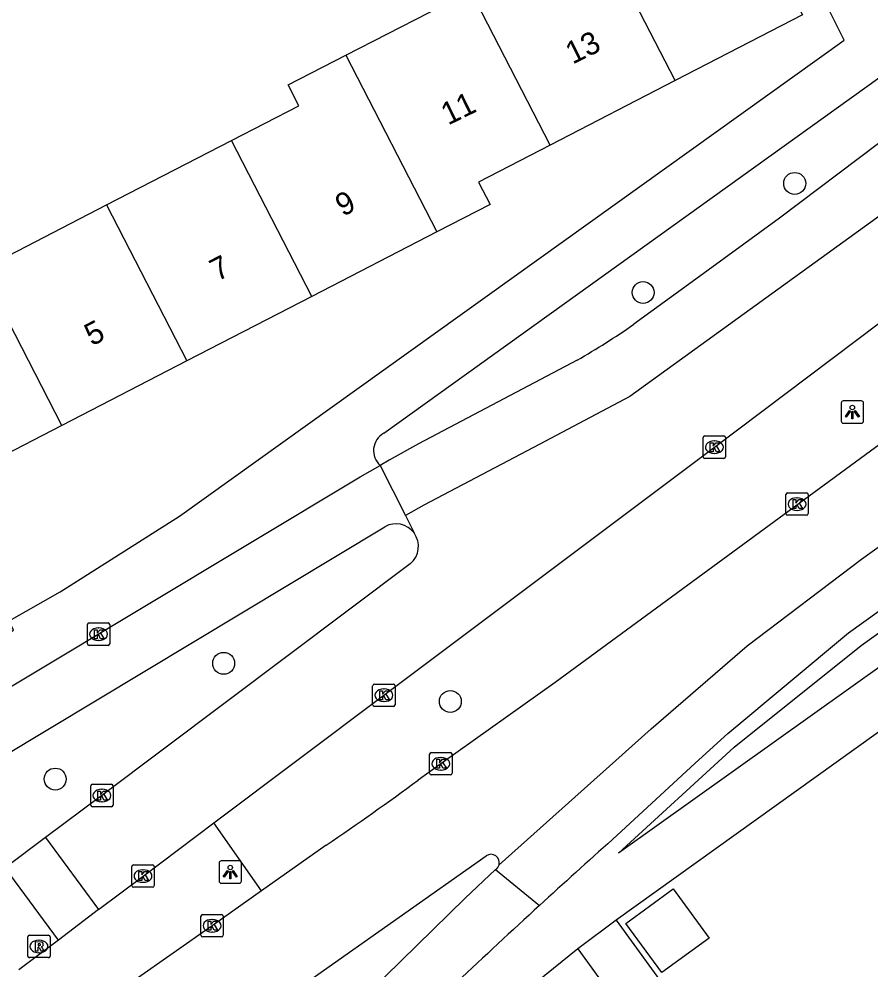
# Model space of a CAD drawing. Extents: x 158461 to 159795, y 387220 to 388672.
# Drawn here: x 159193.22 to 159231.25, y 387763.85 to 387806.3 of the extents above; entities that cross this region are included whole.
import ezdxf

# ---------------------------------------------------------------- set-up
doc = ezdxf.new("R2010")
doc.units = 0
for name, color, linetype in [('IMGEO_Berm_groen', 7, 'Continuous'), ('IMGEO_Boom', 7, 'Continuous'), ('IMGEO_Fietspad_open', 7, 'Continuous'), ('IMGEO_Kolk', 7, 'Continuous'), ('IMGEO_Lichtpunt', 7, 'Continuous'), ('IMGEO_Muur', 7, 'Continuous'), ('IMGEO_Pand', 7, 'Continuous'), ('IMGEO_Pand_nummerreeks', 7, 'Continuous'), ('IMGEO_Rijbaan_lokaal_gesloten', 7, 'Continuous'), ('IMGEO_Rioolput', 7, 'Continuous'), ('IMGEO_Voetpad_open', 7, 'Continuous')]:
    doc.layers.add(name, color=color, linetype=linetype)

msp = doc.modelspace()

# ---------------------------------------------------------------- linework, layer by layer
at = {"layer": 'IMGEO_Berm_groen'}
msp.add_lwpolyline([(159204.04, 387767.381), (159201.915, 387770.417)], dxfattribs=at)
at = {"layer": 'IMGEO_Boom'}
for centre in [(159227.844, 387798.958), (159221.076, 387794.088), (159202.352, 387777.538), (159212.47, 387775.836), (159194.832, 387772.371)]:
    msp.add_circle(centre, 0.489, dxfattribs=at)
at = {"layer": 'IMGEO_Fietspad_open'}
for points in [[(159183.546, 387770.917), (159187.81, 387773.495), (159188.686, 387774.005), (159208.439, 387785.867), (159208.888, 387786.12), (159209.337, 387786.373)], [(159189.389, 387771.511), (159190.225, 387772.028), (159209.549, 387783.637)], [(159214.491, 387768.328), (159213.131, 387767.053), (159199.59, 387753.792), (159198.894, 387753.089), (159198.822, 387753.027)]]:
    msp.add_lwpolyline(points, dxfattribs=at)
for centre, radius, start, end in [((159210.04, 387782.757), 1.007, 36.5326, 119.1576), ((159441.931, 387520.228), 334.072, 132.45033, 134.17723)]:
    msp.add_arc(centre, radius, start, end, dxfattribs=at)
at = {"layer": 'IMGEO_Kolk'}
for p, q in [((159223.756, 387786.758), (159223.756, 387787.61)), ((159223.831, 387787.684), (159224.683, 387787.684)), ((159224.757, 387787.61), (159224.757, 387786.758)), ((159224.244, 387787.464), (159224.269, 387787.464)), ((159224.683, 387786.684), (159223.831, 387786.684)), ((159224.267, 387786.904), (159224.242, 387786.904)), ((159227.449, 387784.218), (159227.449, 387785.07)), ((159227.524, 387785.144), (159228.376, 387785.144)), ((159228.45, 387785.07), (159228.45, 387784.218)), ((159227.937, 387784.924), (159227.962, 387784.924)), ((159228.376, 387784.144), (159227.524, 387784.144)), ((159227.96, 387784.364), (159227.935, 387784.364)), ((159196.267, 387778.412), (159196.267, 387779.264)), ((159196.342, 387779.338), (159197.194, 387779.338)), ((159196.755, 387779.118), (159196.78, 387779.118)), ((159197.268, 387779.264), (159197.268, 387778.412)), ((159197.194, 387778.338), (159196.342, 387778.338)), ((159196.778, 387778.558), (159196.753, 387778.558)), ((159209.003, 387775.686), (159209.003, 387776.538)), ((159209.078, 387776.612), (159209.93, 387776.612)), ((159210.004, 387776.538), (159210.004, 387775.686)), ((159209.491, 387776.392), (159209.516, 387776.392)), ((159209.514, 387775.832), (159209.489, 387775.832)), ((159209.93, 387775.612), (159209.078, 387775.612)), ((159211.622, 387773.554), (159212.474, 387773.554)), ((159211.547, 387772.628), (159211.547, 387773.48)), ((159212.035, 387773.334), (159212.06, 387773.334)), ((159212.548, 387773.48), (159212.548, 387772.628)), ((159212.058, 387772.774), (159212.033, 387772.774)), ((159212.474, 387772.554), (159211.622, 387772.554)), ((159196.415, 387771.211), (159196.415, 387772.063)), ((159196.49, 387772.137), (159197.342, 387772.137)), ((159196.903, 387771.917), (159196.928, 387771.917)), ((159197.416, 387772.063), (159197.416, 387771.211)), ((159197.342, 387771.137), (159196.49, 387771.137)), ((159196.926, 387771.357), (159196.901, 387771.357)), ((159198.25, 387767.616), (159198.25, 387768.468)), ((159198.325, 387768.542), (159199.177, 387768.542)), ((159199.251, 387768.468), (159199.251, 387767.616)), ((159198.738, 387768.322), (159198.763, 387768.322)), ((159198.761, 387767.762), (159198.736, 387767.762)), ((159199.177, 387767.542), (159198.325, 387767.542)), ((159201.41, 387766.324), (159202.262, 387766.324)), ((159201.335, 387765.398), (159201.335, 387766.25)), ((159201.823, 387766.104), (159201.848, 387766.104)), ((159202.336, 387766.25), (159202.336, 387765.398)), ((159201.846, 387765.544), (159201.821, 387765.544)), ((159202.262, 387765.324), (159201.41, 387765.324))]:
    msp.add_line(p, q, dxfattribs=at)
for points in [[(159223.756, 387786.758), (159223.756, 387787.61)], [(159223.831, 387787.684), (159224.683, 387787.684)], [(159224.757, 387787.61), (159224.757, 387786.758)], [(159224.077, 387787.384), (159224.2, 387787.384), (159224.2, 387787.233), (159224.33, 387787.384), (159224.494, 387787.384), (159224.348, 387787.233), (159224.501, 387786.984), (159224.349, 387786.984), (159224.264, 387787.148), (159224.2, 387787.081), (159224.2, 387786.984), (159224.077, 387786.984), (159224.077, 387787.384)], [(159224.683, 387786.684), (159223.831, 387786.684)], [(159227.449, 387784.218), (159227.449, 387785.07)], [(159227.524, 387785.144), (159228.376, 387785.144)], [(159228.45, 387785.07), (159228.45, 387784.218)], [(159227.77, 387784.844), (159227.893, 387784.844), (159227.893, 387784.693), (159228.023, 387784.844), (159228.187, 387784.844), (159228.041, 387784.693), (159228.194, 387784.444), (159228.042, 387784.444), (159227.957, 387784.608), (159227.893, 387784.541), (159227.893, 387784.444), (159227.77, 387784.444), (159227.77, 387784.844)], [(159228.376, 387784.144), (159227.524, 387784.144)], [(159196.267, 387778.412), (159196.267, 387779.264)], [(159196.342, 387779.338), (159197.194, 387779.338)], [(159197.268, 387779.264), (159197.268, 387778.412)], [(159196.588, 387779.038), (159196.711, 387779.038), (159196.711, 387778.887), (159196.841, 387779.038), (159197.005, 387779.038), (159196.859, 387778.887), (159197.012, 387778.638), (159196.86, 387778.638), (159196.775, 387778.802), (159196.711, 387778.735), (159196.711, 387778.638), (159196.588, 387778.638), (159196.588, 387779.038)], [(159197.194, 387778.338), (159196.342, 387778.338)], [(159209.003, 387775.686), (159209.003, 387776.538)], [(159209.078, 387776.612), (159209.93, 387776.612)], [(159210.004, 387776.538), (159210.004, 387775.686)], [(159209.324, 387776.312), (159209.447, 387776.312), (159209.447, 387776.161), (159209.577, 387776.312), (159209.741, 387776.312), (159209.595, 387776.161), (159209.748, 387775.912), (159209.596, 387775.912), (159209.511, 387776.076), (159209.447, 387776.009), (159209.447, 387775.912), (159209.324, 387775.912), (159209.324, 387776.312)], [(159209.93, 387775.612), (159209.078, 387775.612)], [(159211.622, 387773.554), (159212.474, 387773.554)], [(159211.547, 387772.628), (159211.547, 387773.48)], [(159211.868, 387773.254), (159211.991, 387773.254), (159211.991, 387773.103), (159212.121, 387773.254), (159212.285, 387773.254), (159212.139, 387773.103), (159212.292, 387772.854), (159212.14, 387772.854), (159212.055, 387773.018), (159211.991, 387772.951), (159211.991, 387772.854), (159211.868, 387772.854), (159211.868, 387773.254)], [(159212.548, 387773.48), (159212.548, 387772.628)], [(159212.474, 387772.554), (159211.622, 387772.554)], [(159196.415, 387771.211), (159196.415, 387772.063)], [(159196.49, 387772.137), (159197.342, 387772.137)], [(159196.736, 387771.837), (159196.859, 387771.837), (159196.859, 387771.686), (159196.989, 387771.837), (159197.153, 387771.837), (159197.007, 387771.686), (159197.16, 387771.437), (159197.008, 387771.437), (159196.923, 387771.601), (159196.859, 387771.534), (159196.859, 387771.437), (159196.736, 387771.437), (159196.736, 387771.837)], [(159197.416, 387772.063), (159197.416, 387771.211)], [(159197.342, 387771.137), (159196.49, 387771.137)], [(159198.25, 387767.616), (159198.25, 387768.468)], [(159198.325, 387768.542), (159199.177, 387768.542)], [(159199.251, 387768.468), (159199.251, 387767.616)], [(159198.571, 387768.242), (159198.694, 387768.242), (159198.694, 387768.091), (159198.824, 387768.242), (159198.988, 387768.242), (159198.842, 387768.091), (159198.995, 387767.842), (159198.843, 387767.842), (159198.758, 387768.006), (159198.694, 387767.939), (159198.694, 387767.842), (159198.571, 387767.842), (159198.571, 387768.242)], [(159199.177, 387767.542), (159198.325, 387767.542)], [(159201.41, 387766.324), (159202.262, 387766.324)], [(159201.335, 387765.398), (159201.335, 387766.25)], [(159201.656, 387766.024), (159201.779, 387766.024), (159201.779, 387765.873), (159201.909, 387766.024), (159202.073, 387766.024), (159201.927, 387765.873), (159202.08, 387765.624), (159201.928, 387765.624), (159201.843, 387765.788), (159201.779, 387765.721), (159201.779, 387765.624), (159201.656, 387765.624), (159201.656, 387766.024)], [(159202.336, 387766.25), (159202.336, 387765.398)], [(159202.262, 387765.324), (159201.41, 387765.324)]]:
    msp.add_lwpolyline(points, dxfattribs=at)
for centre, start, end in [((159223.833, 387787.608), 91.552, 178.448), ((159223.833, 387787.608), 91.552, 178.448), ((159224.681, 387787.608), 1.552, 88.448), ((159224.681, 387787.608), 1.552, 88.448), ((159223.833, 387786.76), 181.552, 268.448), ((159223.833, 387786.76), 181.552, 268.448), ((159224.681, 387786.76), 271.552, 358.448), ((159224.681, 387786.76), 271.552, 358.448), ((159227.526, 387785.068), 91.552, 178.448), ((159227.526, 387785.068), 91.552, 178.448), ((159228.374, 387785.068), 1.552, 88.448), ((159228.374, 387785.068), 1.552, 88.448), ((159227.526, 387784.22), 181.552, 268.448), ((159227.526, 387784.22), 181.552, 268.448), ((159228.374, 387784.22), 271.552, 358.448), ((159228.374, 387784.22), 271.552, 358.448), ((159196.344, 387779.262), 91.552, 178.448), ((159196.344, 387779.262), 91.552, 178.448), ((159197.192, 387779.262), 1.552, 88.448), ((159197.192, 387779.262), 1.552, 88.448), ((159196.344, 387778.414), 181.552, 268.448), ((159196.344, 387778.414), 181.552, 268.448), ((159197.192, 387778.414), 271.552, 358.448), ((159197.192, 387778.414), 271.552, 358.448), ((159209.08, 387776.536), 91.552, 178.448), ((159209.08, 387776.536), 91.552, 178.448), ((159209.928, 387776.536), 1.552, 88.448), ((159209.928, 387776.536), 1.552, 88.448), ((159209.08, 387775.688), 181.552, 268.448), ((159209.08, 387775.688), 181.552, 268.448), ((159209.928, 387775.688), 271.552, 358.448), ((159209.928, 387775.688), 271.552, 358.448), ((159211.624, 387773.478), 91.552, 178.448), ((159211.624, 387773.478), 91.552, 178.448), ((159212.472, 387773.478), 1.552, 88.448), ((159212.472, 387773.478), 1.552, 88.448), ((159211.624, 387772.63), 181.552, 268.448), ((159211.624, 387772.63), 181.552, 268.448), ((159212.472, 387772.63), 271.552, 358.448), ((159212.472, 387772.63), 271.552, 358.448), ((159196.492, 387772.061), 91.552, 178.448), ((159196.492, 387772.061), 91.552, 178.448), ((159197.34, 387772.061), 1.552, 88.448), ((159197.34, 387772.061), 1.552, 88.448), ((159196.492, 387771.213), 181.552, 268.448), ((159196.492, 387771.213), 181.552, 268.448), ((159197.34, 387771.213), 271.552, 358.448), ((159197.34, 387771.213), 271.552, 358.448), ((159198.327, 387768.466), 91.552, 178.448), ((159198.327, 387768.466), 91.552, 178.448), ((159199.175, 387768.466), 1.552, 88.448), ((159199.175, 387768.466), 1.552, 88.448), ((159198.327, 387767.618), 181.552, 268.448), ((159198.327, 387767.618), 181.552, 268.448), ((159199.175, 387767.618), 271.552, 358.448), ((159199.175, 387767.618), 271.552, 358.448), ((159201.412, 387766.248), 91.552, 178.448), ((159201.412, 387766.248), 91.552, 178.448), ((159202.26, 387766.248), 1.552, 88.448), ((159202.26, 387766.248), 1.552, 88.448), ((159201.412, 387765.4), 181.552, 268.448), ((159201.412, 387765.4), 181.552, 268.448), ((159202.26, 387765.4), 271.552, 358.448), ((159202.26, 387765.4), 271.552, 358.448)]:
    msp.add_arc(centre, 0.0765, start, end, dxfattribs=at)
for centre, major_axis, ratio, start_param, end_param in [((159224.243, 387787.184), (-0.387, 0.002), 0.722429, 4.712389, 7.853982), ((159224.268, 387787.184), (-0.39, 0.002), 0.717154, 1.570796, 4.712389), ((159227.936, 387784.644), (-0.387, 0.002), 0.722429, 4.712389, 7.853982), ((159227.961, 387784.644), (-0.39, 0.002), 0.717154, 1.570796, 4.712389), ((159196.754, 387778.838), (-0.387, 0.002), 0.722429, 4.712389, 7.853982), ((159196.779, 387778.838), (-0.39, 0.002), 0.717154, 1.570796, 4.712389), ((159209.49, 387776.112), (-0.387, 0.002), 0.722429, 4.712389, 7.853982), ((159209.515, 387776.112), (-0.39, 0.002), 0.717154, 1.570796, 4.712389), ((159212.034, 387773.054), (-0.387, 0.002), 0.722429, 4.712389, 7.853982), ((159212.059, 387773.054), (-0.39, 0.002), 0.717154, 1.570796, 4.712389), ((159196.902, 387771.637), (-0.387, 0.002), 0.722429, 4.712389, 7.853982), ((159196.927, 387771.637), (-0.39, 0.002), 0.717154, 1.570796, 4.712389), ((159198.737, 387768.042), (-0.387, 0.002), 0.722429, 4.712389, 7.853982), ((159198.762, 387768.042), (-0.39, 0.002), 0.717154, 1.570796, 4.712389), ((159201.822, 387765.824), (-0.387, 0.002), 0.722429, 4.712389, 7.853982), ((159201.847, 387765.824), (-0.39, 0.002), 0.717154, 1.570796, 4.712389)]:
    msp.add_ellipse(centre, major_axis=major_axis, ratio=ratio, start_param=start_param, end_param=end_param, dxfattribs=at)
at = {"layer": 'IMGEO_Lichtpunt'}
for p, q in [((159230.821, 387789.253), (159230.013, 387789.253)), ((159230.821, 387789.253), (159230.013, 387789.253)), ((159229.919, 387789.158), (159229.919, 387788.351)), ((159229.919, 387789.158), (159229.919, 387788.351)), ((159230.915, 387788.351), (159230.915, 387789.158)), ((159230.915, 387788.351), (159230.915, 387789.158)), ((159230.013, 387788.257), (159230.821, 387788.257)), ((159230.013, 387788.257), (159230.821, 387788.257)), ((159202.148, 387768.625), (159202.148, 387767.818)), ((159202.148, 387768.625), (159202.148, 387767.818)), ((159203.05, 387768.72), (159202.242, 387768.72)), ((159203.05, 387768.72), (159202.242, 387768.72)), ((159203.144, 387767.818), (159203.144, 387768.625)), ((159203.144, 387767.818), (159203.144, 387768.625)), ((159202.242, 387767.724), (159203.05, 387767.724)), ((159202.242, 387767.724), (159203.05, 387767.724))]:
    msp.add_line(p, q, dxfattribs=at)
for points in [[(159230.293, 387788.822), (159230.332, 387788.794), (159230.144, 387788.532), (159230.106, 387788.559), (159230.293, 387788.822)], [(159230.505, 387788.794), (159230.543, 387788.821), (159230.73, 387788.559), (159230.691, 387788.531), (159230.505, 387788.794)], [(159230.395, 387788.774), (159230.442, 387788.774), (159230.442, 387788.452), (159230.395, 387788.452), (159230.395, 387788.774)], [(159202.522, 387768.289), (159202.561, 387768.261), (159202.373, 387767.999), (159202.335, 387768.026), (159202.522, 387768.289)], [(159202.624, 387768.241), (159202.671, 387768.241), (159202.671, 387767.919), (159202.624, 387767.919), (159202.624, 387768.241)], [(159202.734, 387768.261), (159202.772, 387768.288), (159202.959, 387768.026), (159202.92, 387767.998), (159202.734, 387768.261)]]:
    msp.add_lwpolyline(points, dxfattribs=at)
for centre in [(159230.418, 387788.956), (159202.647, 387768.423)]:
    msp.add_circle(centre, 0.0994, dxfattribs=at)
for centre, start, end in [((159230.013, 387789.158), 90, 180), ((159230.013, 387789.158), 90, 180), ((159230.821, 387789.158), 0, 90), ((159230.821, 387789.158), 0, 90), ((159230.013, 387788.351), 180, 270), ((159230.013, 387788.351), 180, 270), ((159230.821, 387788.351), 270, 0), ((159230.821, 387788.351), 270, 360), ((159202.242, 387768.625), 90, 180), ((159202.242, 387768.625), 90, 180), ((159203.05, 387768.625), 0, 90), ((159203.05, 387768.625), 0, 90), ((159202.242, 387767.818), 180, 270), ((159202.242, 387767.818), 180, 270), ((159203.05, 387767.818), 270, 0), ((159203.05, 387767.818), 270, 360)]:
    msp.add_arc(centre, 0.0946, start, end, dxfattribs=at)
at = {"layer": 'IMGEO_Muur'}
msp.add_lwpolyline([(159303.107, 387825.734), (159219.866, 387766.077)], dxfattribs=at)
at = {"layer": 'IMGEO_Pand'}
for points in [[(159218.957, 387810.435), (159224.641, 387813.368), (159228.194, 387806.484), (159222.51, 387803.551)], [(159222.51, 387803.551), (159218.957, 387810.435)], [(159207.8, 387804.678), (159213.379, 387807.557)], [(159216.931, 387800.672), (159213.379, 387807.557)], [(159202.697, 387800.876), (159205.705, 387802.428), (159205.229, 387803.351), (159207.8, 387804.678)], [(159207.8, 387804.678), (159211.87, 387796.792)], [(159222.51, 387803.551), (159216.931, 387800.672)], [(159197.118, 387797.997), (159202.697, 387800.876)], [(159206.291, 387793.913), (159202.697, 387800.876)], [(159216.931, 387800.672), (159213.726, 387799.018), (159214.243, 387798.016), (159211.87, 387796.792)], [(159191.54, 387795.119), (159197.118, 387797.997)], [(159197.118, 387797.997), (159200.712, 387791.034)], [(159211.87, 387796.792), (159206.291, 387793.913)], [(159195.133, 387788.155), (159191.54, 387795.119)], [(159206.291, 387793.913), (159200.712, 387791.034)], [(159200.712, 387791.034), (159195.133, 387788.155)], [(159195.133, 387788.155), (159189.555, 387785.276)], [(159224.026, 387765.272), (159221.912, 387763.731), (159220.309, 387765.93), (159222.423, 387767.471), (159224.026, 387765.272)]]:
    msp.add_lwpolyline(points, dxfattribs=at)
at = {"layer": 'IMGEO_Rijbaan_lokaal_gesloten'}
for points in [[(159362.464, 387894.175), (159362.457, 387894.163), (159361.328, 387892.332), (159359.814, 387890.367), (159358.762, 387889.229), (159357.6, 387888.103), (159356.584, 387887.282), (159350.468, 387882.827), (159305.218, 387850.303), (159292.142, 387840.964), (159262.355, 387819.579), (159234.134, 387799.313), (159220.483, 387789.45), (159216.18, 387787.175), (159211.29, 387784.59), (159210.462, 387784.13)], [(159214.645, 387768.545), (159219.859, 387773.204), (159221.438, 387774.616), (159225.716, 387778.318), (159230.826, 387782.182), (159243.853, 387791.543), (159266.445, 387807.778), (159283.029, 387819.662), (159301.822, 387833.141), (159320.964, 387846.898), (159342.201, 387862.095), (159364.131, 387877.774), (159366.64, 387879.613)], [(159201.915, 387770.417), (159209.504, 387776.112), (159224.257, 387787.184), (159238.999, 387798.281), (159246.695, 387804.016), (159250.763, 387806.969), (159261.561, 387814.696), (159267.608, 387819.082), (159278.694, 387827.124), (159294.287, 387838.368)], [(159297.206, 387834.328), (159280.691, 387822.526), (159270.371, 387815.125), (159259.925, 387807.634), (159241.009, 387794.063), (159231.446, 387787.171), (159217.149, 387776.687), (159212.048, 387773.054), (159211.04, 387772.323)], [(159219.705, 387769.67), (159223.407, 387773.077), (159224.861, 387774.398), (159230.249, 387778.893), (159256.111, 387797.449), (159285.066, 387818.293), (159303.798, 387831.383)], [(159231.582, 387800.745), (159227.168, 387797.404), (159223.103, 387794.452), (159220.664, 387792.671)], [(159218.134, 387791.068), (159211.042, 387787.331), (159209.745, 387786.603), (159209.337, 387786.373)], [(159209.337, 387786.373), (159210.462, 387784.13)], [(159210.462, 387784.13), (159210.849, 387783.357)], [(159210.683, 387781.984), (159196.916, 387771.637), (159194.404, 387769.757)], [(159196.77, 387766.545), (159198.751, 387768.042), (159201.915, 387770.417)], [(159194.404, 387769.757), (159192.602, 387768.409)], [(159194.404, 387769.757), (159196.77, 387766.545)], [(159206.931, 387769.424), (159204.04, 387767.381)], [(159196.748, 387756.729), (159202.425, 387760.735), (159214.068, 387768.944)], [(159194.975, 387765.188), (159192.602, 387768.409)], [(159214.491, 387768.328), (159216.449, 387766.728)], [(159204.04, 387767.381), (159201.836, 387765.824), (159194.871, 387760.944), (159194.829, 387760.914)], [(159196.77, 387766.545), (159194.975, 387765.188)], [(159194.975, 387765.188), (159193.204, 387763.85)]]:
    msp.add_lwpolyline(points, dxfattribs=at)
for centre, radius, start, end in [((159200.352, 387821.931), 35.619, 299.9486, 304.7678), ((159210.04, 387782.758), 1.007, 309.7253, 36.4871), ((159127.343, 387886.592), 141.642, 304.18677, 306.22104), ((159424.864, 387539.341), 308.45, 131.69222, 132.50736), ((159214.284, 387768.639), 0.373, 345.3399, 125.3318), ((159214.286, 387768.637), 0.371, 303.6014, 345.6737)]:
    msp.add_arc(centre, radius, start, end, dxfattribs=at)
at = {"layer": 'IMGEO_Rioolput'}
for p, q in [((159193.606, 387764.474), (159193.606, 387765.326)), ((159193.681, 387765.4), (159194.533, 387765.4)), ((159194.094, 387765.18), (159194.119, 387765.18)), ((159194.607, 387765.326), (159194.607, 387764.474)), ((159194.117, 387764.62), (159194.092, 387764.62)), ((159194.533, 387764.4), (159193.681, 387764.4))]:
    msp.add_line(p, q, dxfattribs=at)
for points in [[(159193.606, 387764.474), (159193.606, 387765.326)], [(159193.681, 387765.4), (159194.533, 387765.4)], [(159194.195, 387765.098), (159193.943, 387765.1), (159193.943, 387764.7)], [(159194.607, 387765.326), (159194.607, 387764.474)], [(159193.943, 387764.7), (159194.067, 387764.7), (159194.067, 387764.862), (159194.078, 387764.862)], [(159194.121, 387765.019), (159194.067, 387765.019), (159194.067, 387764.938)], [(159194.067, 387764.938), (159194.119, 387764.938)], [(159194.125, 387764.833), (159194.196, 387764.7), (159194.336, 387764.7), (159194.271, 387764.826)], [(159194.533, 387764.4), (159193.681, 387764.4)]]:
    msp.add_lwpolyline(points, dxfattribs=at)
for centre, radius, start, end in [((159193.683, 387765.324), 0.0765, 91.552, 178.448), ((159193.683, 387765.324), 0.0765, 91.552, 178.448), ((159194.194, 387764.988), 0.109, 350.3612, 89.416), ((159194.531, 387765.324), 0.0765, 1.552, 88.448), ((159194.531, 387765.324), 0.0765, 1.552, 88.448), ((159194.077, 387764.809), 0.0533, 26.0293, 88.6989), ((159194.103, 387765.127), 0.19, 274.7715, 282.9687), ((159194.127, 387764.923), 0.0964, 77.0061, 93.1865), ((159194.141, 387764.98), 0.0378, 276.6634, 79.6772), ((159194.192, 387764.988), 0.112, 277.5842, 350.9817), ((159194.176, 387764.773), 0.108, 29.5134, 73.7905), ((159193.683, 387764.476), 0.0765, 181.552, 268.448), ((159193.683, 387764.476), 0.0765, 181.552, 268.448), ((159194.531, 387764.476), 0.0765, 271.552, 358.448), ((159194.531, 387764.476), 0.0765, 271.552, 358.448)]:
    msp.add_arc(centre, radius, start, end, dxfattribs=at)
for centre, major_axis, ratio, start_param, end_param in [((159194.093, 387764.9), (-0.387, 0.002), 0.722429, 4.712389, 7.853982), ((159194.118, 387764.9), (-0.39, 0.002), 0.717154, 1.570796, 4.712389)]:
    msp.add_ellipse(centre, major_axis=major_axis, ratio=ratio, start_param=start_param, end_param=end_param, dxfattribs=at)
at = {"layer": 'IMGEO_Voetpad_open'}
for points in [[(159273.442, 387807.19), (159219.977, 387769.057), (159225.144, 387773.8), (159230.812, 387778.327), (159301.249, 387828.914), (159302.094, 387827.801), (159273.442, 387807.19)], [(159307.132, 387828.619), (159303.107, 387825.734), (159219.866, 387766.077)], [(159184.183, 387774.695), (159186.197, 387775.791), (159186.627, 387775.2), (159191.082, 387777.895), (159190.838, 387778.376), (159191.529, 387778.714), (159191.735, 387778.258), (159192.968, 387779.018), (159192.776, 387779.434), (159195.055, 387780.729), (159200.377, 387784.101), (159230.052, 387805.353), (159229.292, 387806.869)], [(159209.5, 387787.805), (159232.218, 387804.111)], [(159219.866, 387766.077), (159218.155, 387764.796)], [(159219.866, 387766.077), (159225.4, 387758.477)], [(159218.155, 387764.796), (159213.819, 387761.288), (159204.282, 387752.237), (159202.211, 387750), (159197.458, 387744.641)], [(159218.155, 387764.796), (159223.591, 387757.291)]]:
    msp.add_lwpolyline(points, dxfattribs=at)
msp.add_arc((159209.925, 387787.031), 0.883, 118.7724, 228.2399, dxfattribs=at)

# ---------------------------------------------------------------- texts
at = {"layer": 'IMGEO_Pand_nummerreeks'}
for s, rotation, p in [('13', 26.103, (159217.93, 387804.261)), ('11', 26.103, (159212.369, 387801.536)), ('9', 27.2952, (159207.67, 387797.46)), ('7', 27.2952, (159202.07, 387794.57)), ('5', 27.2952, (159196.47, 387791.68))]:
    msp.add_text(s, height=1, rotation=rotation, dxfattribs=at).set_placement(p)

doc.saveas('drawing.dxf')
